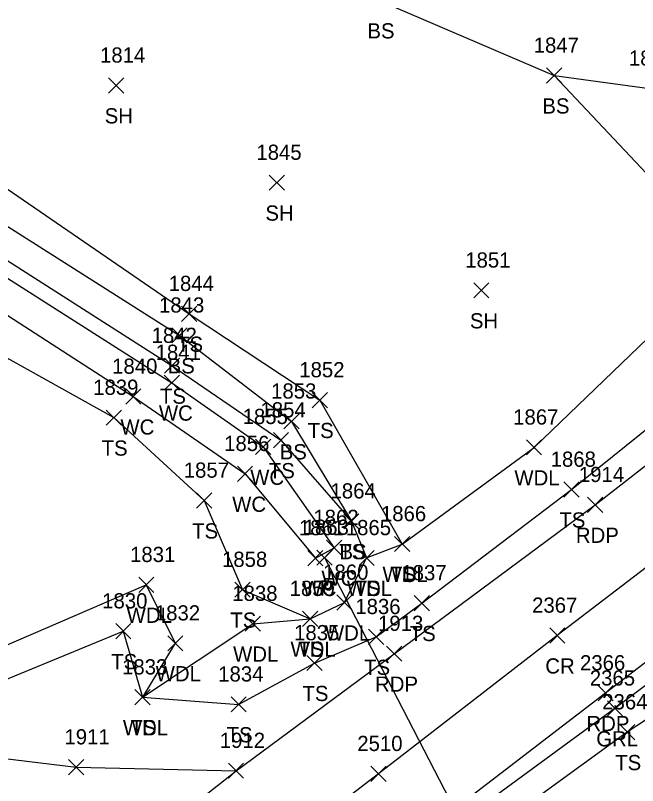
# Model space of a CAD drawing. Extents: x 1505656 to 1508446, y 700805 to 703031.
# Drawn here: x 1506624.7 to 1506706.6, y 702191.6 to 702293 of the extents above; entities that cross this region are included whole.
import ezdxf

# ---------------------------------------------------------------- set-up
doc = ezdxf.new("R2010")
doc.units = 0
for name, color, linetype in [('D_A', 7, 'Continuous'), ('D_I', 7, 'Continuous'), ('D_TIC', 7, 'Continuous'), ('DCP', 7, 'Continuous'), ('L_A', 7, 'Continuous'), ('L_I', 7, 'Continuous'), ('L_TIC', 7, 'Continuous'), ('LAWA', 7, 'Continuous'), ('LAWE', 7, 'Continuous'), ('LELB', 7, 'Continuous'), ('P_A', 7, 'Continuous'), ('P_I', 7, 'Continuous'), ('P_TIC', 7, 'Continuous'), ('PET', 7, 'Continuous'), ('PRC', 7, 'Continuous'), ('R_A', 7, 'Continuous'), ('R_I', 7, 'Continuous'), ('R_TIC', 7, 'Continuous'), ('RDG', 7, 'Continuous'), ('RGR', 7, 'Continuous')]:
    doc.layers.add(name, color=color, linetype=linetype)

msp = doc.modelspace()

# ---------------------------------------------------------------- linework, layer by layer
at = {"layer": 'D_TIC'}
for points in [[(1506664.38, 702220.63), (1506666.38, 702222.63)], [(1506666.38, 702220.63), (1506664.38, 702222.63)]]:
    msp.add_lwpolyline(points, dxfattribs=at)
at = {"layer": 'DCP'}
msp.add_lwpolyline([(1506665.38, 702221.63), (1506693.51, 702167.15)], dxfattribs=at)
at = {"layer": 'L_TIC'}
for points in [[(1506694.6, 702284.04), (1506696.6, 702286.04)], [(1506696.6, 702284.04), (1506694.6, 702286.04)], [(1506694.6, 702284.04), (1506696.6, 702286.04)], [(1506696.6, 702284.04), (1506694.6, 702286.04)], [(1506636.99, 702282.74), (1506638.99, 702284.74)], [(1506638.99, 702282.74), (1506636.99, 702284.74)], [(1506658.13, 702269.95), (1506660.13, 702271.95)], [(1506660.13, 702269.95), (1506658.13, 702271.95)], [(1506685.02, 702255.78), (1506687.02, 702257.78)], [(1506687.02, 702255.78), (1506685.02, 702257.78)], [(1506646.59, 702252.7), (1506648.59, 702254.7)], [(1506648.59, 702252.7), (1506646.59, 702254.7)], [(1506645.32, 702249.86), (1506647.32, 702251.86)], [(1506647.32, 702249.86), (1506645.32, 702251.86)], [(1506644.34, 702245.87), (1506646.34, 702247.87)], [(1506646.34, 702245.87), (1506644.34, 702247.87)], [(1506644.31, 702243.64), (1506646.31, 702245.64)], [(1506646.31, 702243.64), (1506644.31, 702245.64)], [(1506639.24, 702241.81), (1506641.24, 702243.81)], [(1506641.24, 702241.81), (1506639.24, 702243.81)], [(1506663.77, 702241.35), (1506665.77, 702243.35)], [(1506665.77, 702241.35), (1506663.77, 702243.35)], [(1506636.67, 702239.04), (1506638.67, 702241.04)], [(1506638.67, 702239.04), (1506636.67, 702241.04)], [(1506660.06, 702238.55), (1506662.06, 702240.55)], [(1506662.06, 702238.55), (1506660.06, 702240.55)], [(1506658.66, 702236.07), (1506660.66, 702238.07)], [(1506660.66, 702236.07), (1506658.66, 702238.07)], [(1506656.31, 702235.2), (1506658.31, 702237.2)], [(1506658.31, 702235.2), (1506656.31, 702237.2)], [(1506691.94, 702235.13), (1506693.94, 702237.13)], [(1506693.94, 702235.13), (1506691.94, 702237.13)], [(1506653.94, 702231.65), (1506655.94, 702233.65)], [(1506655.94, 702231.65), (1506653.94, 702233.65)], [(1506696.87, 702229.58), (1506698.87, 702231.58)], [(1506698.87, 702229.58), (1506696.87, 702231.58)], [(1506648.57, 702228.14), (1506650.57, 702230.14)], [(1506650.57, 702228.14), (1506648.57, 702230.14)], [(1506667.92, 702225.41), (1506669.92, 702227.41)], [(1506669.92, 702225.41), (1506667.92, 702227.41)], [(1506667.92, 702225.41), (1506669.92, 702227.41)], [(1506669.92, 702225.41), (1506667.92, 702227.41)], [(1506665.67, 702221.92), (1506667.67, 702223.92)], [(1506667.67, 702221.92), (1506665.67, 702223.92)], [(1506665.67, 702221.92), (1506667.67, 702223.92)], [(1506667.67, 702221.92), (1506665.67, 702223.92)], [(1506674.61, 702222.42), (1506676.61, 702224.42)], [(1506676.61, 702222.42), (1506674.61, 702224.42)], [(1506674.61, 702222.42), (1506676.61, 702224.42)], [(1506676.61, 702222.42), (1506674.61, 702224.42)], [(1506663.19, 702220.57), (1506665.19, 702222.57)], [(1506665.19, 702220.57), (1506663.19, 702222.57)], [(1506669.93, 702220.58), (1506671.93, 702222.58)], [(1506671.93, 702220.58), (1506669.93, 702222.58)], [(1506669.93, 702220.58), (1506671.93, 702222.58)], [(1506671.93, 702220.58), (1506669.93, 702222.58)], [(1506640.95, 702217.05), (1506642.95, 702219.05)], [(1506642.95, 702217.05), (1506640.95, 702219.05)], [(1506653.6, 702216.41), (1506655.6, 702218.41)], [(1506655.6, 702216.41), (1506653.6, 702218.41)], [(1506667.03, 702214.72), (1506669.03, 702216.72)], [(1506669.03, 702214.72), (1506667.03, 702216.72)], [(1506677.19, 702214.65), (1506679.19, 702216.65)], [(1506679.19, 702214.65), (1506677.19, 702216.65)], [(1506662.5, 702212.58), (1506664.5, 702214.58)], [(1506664.5, 702212.58), (1506662.5, 702214.58)], [(1506662.5, 702212.58), (1506664.5, 702214.58)], [(1506664.5, 702212.58), (1506662.5, 702214.58)], [(1506654.95, 702211.94), (1506656.95, 702213.94)], [(1506656.95, 702211.94), (1506654.95, 702213.94)], [(1506637.93, 702210.95), (1506639.93, 702212.95)], [(1506639.93, 702210.95), (1506637.93, 702212.95)], [(1506644.77, 702209.36), (1506646.77, 702211.36)], [(1506646.77, 702209.36), (1506644.77, 702211.36)], [(1506671.19, 702210.2), (1506673.19, 702212.2)], [(1506673.19, 702210.2), (1506671.19, 702212.2)], [(1506663.08, 702206.76), (1506665.08, 702208.76)], [(1506665.08, 702206.76), (1506663.08, 702208.76)], [(1506640.46, 702202.26), (1506642.46, 702204.26)], [(1506642.46, 702202.26), (1506640.46, 702204.26)], [(1506640.46, 702202.26), (1506642.46, 702204.26)], [(1506642.46, 702202.26), (1506640.46, 702204.26)], [(1506653.1, 702201.33), (1506655.1, 702203.33)], [(1506655.1, 702201.33), (1506653.1, 702203.33)], [(1506704.21, 702197.67), (1506706.21, 702199.67)], [(1506706.21, 702197.67), (1506704.21, 702199.67)]]:
    msp.add_lwpolyline(points, dxfattribs=at)
at = {"layer": 'LAWA'}
msp.add_lwpolyline([(1506477.11, 702338.78), (1506505.06, 702319.4), (1506519.83, 702306.48), (1506544.92, 702278.68), (1506587.97, 702243.37), (1506602.7, 702221.47), (1506611.67, 702210.59), (1506619.38, 702208.31), (1506641.95, 702218.05), (1506645.77, 702210.36), (1506641.46, 702203.26), (1506655.95, 702212.94), (1506663.5, 702213.58), (1506668.03, 702215.72), (1506670.93, 702221.58), (1506675.61, 702223.42), (1506692.94, 702236.13), (1506718.23, 702260.42), (1506729.5, 702264.44), (1506742.86, 702284.75), (1506741.94, 702295.33)], dxfattribs=at)
at = {"layer": 'LAWE'}
for points in [[(1506490.28, 702352.03), (1506521, 702337.02), (1506544.56, 702324.54), (1506577.35, 702297.85), (1506603.49, 702271.23), (1506645.31, 702244.64), (1506657.31, 702236.2), (1506666.67, 702222.92)], [(1506488.57, 702349.6), (1506518.67, 702334.27), (1506541.33, 702321.04), (1506575.21, 702295.05), (1506600.92, 702268.2), (1506640.24, 702242.81), (1506654.94, 702232.65), (1506664.19, 702221.57), (1506666.67, 702222.92)]]:
    msp.add_lwpolyline(points, dxfattribs=at)
at = {"layer": 'LELB'}
for points in [[(1506554.73, 702410.63), (1506571.62, 702388.81), (1506587.3, 702364.68), (1506595.49, 702347.32), (1506603.05, 702331.19), (1506631.52, 702309.43), (1506643.87, 702302.81), (1506672.58, 702294.92), (1506695.6, 702285.04), (1506708.11, 702283.35), (1506723.52, 702281.47), (1506742.86, 702284.75), (1506754.22, 702281.75), (1506785.62, 702304.86), (1506788.07, 702315.41), (1506788.97, 702329.45), (1506782.07, 702339.23), (1506762.2, 702353.33), (1506734.82, 702369.43)], [(1506524.02, 702379.4), (1506546.11, 702363.25), (1506568.43, 702344.57), (1506583.69, 702335.66), (1506592.02, 702306.47), (1506605.6, 702288.64), (1506610.44, 702279.18), (1506647.59, 702253.7), (1506664.77, 702242.35), (1506675.61, 702223.42)], [(1506517.86, 702372.04), (1506540.4, 702356.24), (1506563.61, 702340.55), (1506580.36, 702332.13), (1506589.17, 702302.55), (1506601.23, 702287.37), (1506607.24, 702275.64), (1506646.32, 702250.86), (1506661.06, 702239.55), (1506668.92, 702226.41)], [(1506493, 702353.6), (1506523.91, 702339.68), (1506547.42, 702326.31), (1506578.46, 702299.78), (1506604.85, 702272.74), (1506645.34, 702246.87), (1506659.66, 702237.07), (1506668.92, 702226.41), (1506670.93, 702221.58)], [(1506487.03, 702347.19), (1506516.48, 702331.54), (1506536.52, 702316.03), (1506569.86, 702291.37), (1506596.61, 702262.95), (1506637.67, 702240.04), (1506649.57, 702229.14), (1506654.6, 702217.41), (1506663.5, 702213.58)], [(1506814.99, 702290.57), (1506813.87, 702286.06), (1506807.84, 702280.49), (1506793.11, 702270.17), (1506781.64, 702259.55), (1506767.7, 702238.11), (1506757.49, 702229.1), (1506750.34, 702222.94), (1506731.66, 702216.02), (1506705.21, 702198.67), (1506682.75, 702182.36), (1506672.52, 702174.64), (1506641.22, 702149.14), (1506609.17, 702121.88), (1506576.09, 702098.53), (1506560.14, 702084.86), (1506543.98, 702068.4), (1506533.32, 702053.62)], [(1506695.6, 702285.04), (1506711.27, 702268.39), (1506718.23, 702260.42)], [(1506544.92, 702278.68), (1506582.68, 702238.27), (1506598.32, 702217.88), (1506606.72, 702207.43), (1506617.6, 702203.18), (1506638.93, 702211.95), (1506641.46, 702203.26), (1506654.1, 702202.33), (1506664.08, 702207.76), (1506672.19, 702211.2), (1506678.19, 702215.65), (1506697.87, 702230.58), (1506723.25, 702251.01), (1506744.84, 702270.48), (1506754.22, 702281.75)]]:
    msp.add_lwpolyline(points, dxfattribs=at)
at = {"layer": 'P_TIC'}
for points in [[(1506699.97, 702227.57), (1506701.97, 702229.57)], [(1506701.97, 702227.57), (1506699.97, 702229.57)], [(1506695, 702210.38), (1506697, 702212.38)], [(1506697, 702210.38), (1506695, 702212.38)], [(1506673.56, 702207.99), (1506675.56, 702209.99)], [(1506675.56, 702207.99), (1506673.56, 702209.99)], [(1506701.36, 702202.8), (1506703.36, 702204.8)], [(1506703.36, 702202.8), (1506701.36, 702204.8)], [(1506652.75, 702192.6), (1506654.75, 702194.6)], [(1506654.75, 702192.6), (1506652.75, 702194.6)], [(1506671.48, 702192.19), (1506673.48, 702194.19)], [(1506673.48, 702192.19), (1506671.48, 702194.19)]]:
    msp.add_lwpolyline(points, dxfattribs=at)
at = {"layer": 'PET'}
for points in [[(1506450.65, 702029.2), (1506459.01, 702027.77), (1506468.15, 702029.49), (1506475.63, 702033.45), (1506492.49, 702050.17), (1506507, 702065.69), (1506526.03, 702085.92), (1506543.4, 702101.89), (1506555.15, 702112.06), (1506575.48, 702129.8), (1506589.02, 702140.73), (1506620.87, 702167.68), (1506653.75, 702193.6), (1506674.56, 702208.99), (1506700.97, 702228.57), (1506728, 702249.61), (1506759.67, 702274.83), (1506793.4, 702301.37), (1506821.19, 702323.11), (1506840.12, 702337.4)], [(1506857.05, 702321.26), (1506820.83, 702294.67), (1506814.99, 702290.57), (1506777.85, 702262.75), (1506747.99, 702238.85), (1506725.92, 702221.9), (1506702.36, 702203.8), (1506679.15, 702185.98), (1506669.5, 702178.34), (1506637.66, 702153.48), (1506604.91, 702127), (1506574.06, 702100.19), (1506542.07, 702070.61), (1506522.55, 702050.29), (1506506.91, 702029.72), (1506498.07, 702013.24), (1506495.48, 702000.5), (1506496.78, 701989.17), (1506504.12, 701976.85)]]:
    msp.add_lwpolyline(points, dxfattribs=at)
at = {"layer": 'PRC'}
msp.add_lwpolyline([(1507099.79, 702434.29), (1507054.12, 702415.31), (1507012.5, 702399.89), (1506976.2, 702386.69), (1506932.66, 702370.41), (1506907.47, 702359.22), (1506868.1, 702338.86), (1506842.67, 702323.4), (1506809.9, 702300.17), (1506770.28, 702269.35), (1506742.25, 702247.51), (1506720.16, 702229.85), (1506696, 702211.38), (1506672.48, 702193.19), (1506662.62, 702185.62), (1506629.64, 702159.4), (1506597.85, 702133.73), (1506566.79, 702107.87), (1506534.18, 702078.28), (1506512.18, 702055.63), (1506496.34, 702038.07), (1506482, 702021.83), (1506469.42, 702008.91)], dxfattribs=at)
at = {"layer": 'R_TIC'}
for points in [[(1506702.59, 702200.8), (1506704.59, 702202.8)], [(1506704.59, 702200.8), (1506702.59, 702202.8)], [(1506631.74, 702193.06), (1506633.74, 702195.06)], [(1506633.74, 702193.06), (1506631.74, 702195.06)], [(1506652.75, 702192.6), (1506654.75, 702194.6)], [(1506654.75, 702192.6), (1506652.75, 702194.6)]]:
    msp.add_lwpolyline(points, dxfattribs=at)
at = {"layer": 'RDG'}
msp.add_lwpolyline([(1506520.5, 702202.93), (1506507.4, 702210.86), (1506483.97, 702233.07), (1506468.5, 702251.01), (1506438.77, 702275.2), (1506423.41, 702290.8), (1506445.37, 702309.02), (1506465.24, 702326.26), (1506484.87, 702307.6), (1506501.93, 702293.1), (1506520.54, 702276.62), (1506545.79, 702252.46), (1506583.99, 702217.25), (1506599.92, 702202.97), (1506609.81, 702199.05), (1506619.72, 702195.64), (1506632.74, 702194.06), (1506653.75, 702193.6)], dxfattribs=at)
at = {"layer": 'RGR'}
msp.add_lwpolyline([(1506752.79, 702233.09), (1506727.8, 702219.94), (1506703.59, 702201.8), (1506680.27, 702184.69), (1506670.61, 702177.25), (1506638.82, 702152.4), (1506605.75, 702125.7), (1506574.75, 702099.53), (1506559.42, 702085.15), (1506543.98, 702068.4), (1506523.47, 702048.35), (1506509.04, 702028.65), (1506499.81, 702012.03), (1506496.91, 702000.42), (1506498.7, 701989.82), (1506504.87, 701977.79), (1506523.25, 701960.02), (1506561.6, 701930.02), (1506583.7, 701912.41)], dxfattribs=at)

# ---------------------------------------------------------------- texts
at = {"layer": 'D_A'}
msp.add_text('P', height=2, dxfattribs=at).set_placement((1506664.75, 702216.63))
at = {"layer": 'D_I'}
msp.add_text('1863', height=2, dxfattribs=at).set_placement((1506662.64, 702224.63))
at = {"layer": 'L_A'}
for s, p in [('BS', (1506671.03, 702289.92)), ('BS', (1506694.04, 702280.04)), ('BS', (1506694.04, 702280.04)), ('SH', (1506636.48, 702278.74)), ('SH', (1506657.62, 702265.95)), ('SH', (1506684.51, 702251.78)), ('TS', (1506646, 702248.7)), ('BS', (1506644.76, 702245.86)), ('TS', (1506643.75, 702241.87)), ('WC', (1506643.61, 702239.64)), ('WC', (1506638.55, 702237.81)), ('TS', (1506663.18, 702237.35)), ('TS', (1506636.08, 702235.04)), ('BS', (1506659.5, 702234.55)), ('TS', (1506658.07, 702232.07)), ('WC', (1506655.62, 702231.2)), ('WDL', (1506690.36, 702231.13)), ('WC', (1506653.25, 702227.65)), ('TS', (1506696.28, 702225.58)), ('TS', (1506647.98, 702224.14)), ('TS', (1506667.33, 702221.41)), ('BS', (1506667.36, 702221.41)), ('WC', (1506664.98, 702217.92)), ('WC', (1506664.98, 702217.92)), ('WDL', (1506673.02, 702218.42)), ('TS', (1506674.02, 702218.42)), ('WC', (1506662.5, 702216.57)), ('WDL', (1506668.34, 702216.58)), ('TS', (1506669.34, 702216.58)), ('WDL', (1506639.37, 702213.05)), ('TS', (1506653.01, 702212.41)), ('WDL', (1506665.45, 702210.72)), ('TS', (1506676.6, 702210.65)), ('WDL', (1506660.92, 702208.58)), ('TS', (1506661.91, 702208.58)), ('WDL', (1506653.37, 702207.94)), ('TS', (1506637.34, 702206.95)), ('WDL', (1506643.19, 702205.36)), ('TS', (1506670.6, 702206.2)), ('TS', (1506662.49, 702202.76)), ('WDL', (1506638.88, 702198.26)), ('TS', (1506639.87, 702198.26)), ('TS', (1506652.51, 702197.33)), ('TS', (1506703.62, 702193.67))]:
    msp.add_text(s, height=2, dxfattribs=at).set_placement(p)
at = {"layer": 'L_I'}
for s, p in [('1847', (1506692.9, 702288.04)), ('1847', (1506692.9, 702288.04)), ('1814', (1506635.87, 702286.74)), ('1848', (1506705.42, 702286.35)), ('1848', (1506705.42, 702286.35)), ('1845', (1506656.43, 702273.95)), ('1851', (1506683.9, 702259.78)), ('1844', (1506644.9, 702256.7)), ('1843', (1506643.63, 702253.86)), ('1842', (1506642.65, 702249.87)), ('1841', (1506643.18, 702247.64)), ('1840', (1506637.46, 702245.81)), ('1852', (1506662.07, 702245.35)), ('1839', (1506634.97, 702243.04)), ('1853', (1506658.37, 702242.55)), ('1854', (1506656.97, 702240.07)), ('1855', (1506654.62, 702239.2)), ('1867', (1506690.2, 702239.13)), ('1856', (1506652.19, 702235.65)), ('1868', (1506695.13, 702233.58)), ('1857', (1506646.88, 702232.14)), ('1864', (1506666.18, 702229.41)), ('1864', (1506666.18, 702229.41)), ('1862', (1506663.93, 702225.92)), ('1862', (1506663.93, 702225.92)), ('1866', (1506672.81, 702226.42)), ('1866', (1506672.81, 702226.42)), ('1861', (1506662.02, 702224.57)), ('1865', (1506668.19, 702224.58)), ('1865', (1506668.19, 702224.58)), ('1831', (1506639.82, 702221.05)), ('1858', (1506651.91, 702220.41)), ('1860', (1506665.21, 702218.72)), ('1837', (1506675.5, 702218.65)), ('1859', (1506660.8, 702216.58)), ('1859', (1506660.8, 702216.58)), ('1838', (1506653.26, 702215.94)), ('1830', (1506636.15, 702214.95)), ('1836', (1506669.44, 702214.2)), ('1832', (1506643.08, 702213.36)), ('1835', (1506661.39, 702210.76)), ('1833', (1506638.77, 702206.26)), ('1833', (1506638.77, 702206.26)), ('1834', (1506651.41, 702205.33)), ('2364', (1506701.91, 702201.67))]:
    msp.add_text(s, height=2, dxfattribs=at).set_placement(p)
at = {"layer": 'P_A'}
for s, p in [('RDP', (1506698.45, 702223.57)), ('CR', (1506694.43, 702206.38)), ('RDP', (1506672.04, 702203.99)), ('RDP', (1506699.84, 702198.8))]:
    msp.add_text(s, height=2, dxfattribs=at).set_placement(p)
at = {"layer": 'P_I'}
for s, p in [('1914', (1506698.84, 702231.57)), ('2367', (1506692.69, 702214.38)), ('1913', (1506672.43, 702211.99)), ('2366', (1506698.99, 702206.8)), ('1912', (1506651.62, 702196.6)), ('2510', (1506669.7, 702196.19))]:
    msp.add_text(s, height=2, dxfattribs=at).set_placement(p)
at = {"layer": 'R_A'}
msp.add_text('GRL', height=2, dxfattribs=at).set_placement((1506701.13, 702196.8))
at = {"layer": 'R_I'}
for s, p in [('2365', (1506700.28, 702204.8)), ('1911', (1506631.19, 702197.06)), ('1912', (1506651.62, 702196.6))]:
    msp.add_text(s, height=2, dxfattribs=at).set_placement(p)

doc.saveas('drawing.dxf')
